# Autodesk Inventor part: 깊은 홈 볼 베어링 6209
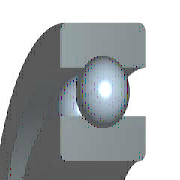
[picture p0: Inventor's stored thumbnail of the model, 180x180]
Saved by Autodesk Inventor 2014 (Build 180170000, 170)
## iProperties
IsCustomPart: 1
Created: 2012-02
Part Number: 깊은 홈 볼 베어링 6209
Material: 강철, 연강
Description: 깊은 그루부 볼 베어링
Document SubType Name: Modeling
Standard: JIS B 1521
Designer: mdu-01
Standards Organization: JIS
Language: ko-KR
Size Designation: 6209 45x85x19
Categories: <MemberInstance><Categories><Category DisplayName="샤프트 부품" InternalName="7f7aeb1f-a693-4053-b835-cee3144e0d98" Mnemonic="SHFT"><Category DisplayName="베어링" Inter
Density: 7.86 g/cm^3
Appearance: 강철(1)
Mass: 366.455 g
Surface Area: 242.591 cm^2
Volume: 46.6228 cm^3
Author: mdu-01
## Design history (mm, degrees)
sketch "스케치" dims "d0" = 10.4 (= -0.26 x WD + 0.26 x BD)
  geometry: L1 (4.3, 32.5)-(14.7, 32.5); L2 (9.5, 32.5)-(9.5, 27.3); L3 (9.5, 32.5)-(9.5, 37.7); L4 (5.636, 29.02)-(0, 29.02); L5 (0, 22.5)-(19, 22.5); L6 (5.636, 35.98)-(0, 35.98); L7 (0, 42.5)-(19, 42.5); L8 (19, 22.5)-(19, 29.02); L9 (13.364, 29.02)-(19, 29.02); L10 (13.364, 35.98)-(19, 35.98); L11 (19, 42.5)-(19, 35.98); L12 (-1.4, 0)-(8.4, 0) reference; L13 (0, -0.3)-(0, 5.3) reference
  constraints: 22 end point, 4 point on line, 2 collinear, 2 perpendicular, 2 symmetric about line, 1 midpoint, 1 parallel, 14 other
  dimensions: "d9" = 45 diameter of L5 L12 (= WD); "d11" = 85 diameter of L7 L12 (= BD); "d12" = 19 distance between parallel lines of L8 L13 (= KB); "d13" = 58.04 diameter of L9 L12 (= 0.326 x BD + 0.674 x WD)
revolve "본체" stored, may be unused: angle "d6" = 90 deg
revolve "볼" stored, may be unused: angle "d7" = 90 deg
pattern_circular "IDS_ARRAYBALL[SIMPL:T]" dims angle "d3" = 360 deg
body "Solid1"
fillet "모깎기1" dims "d1" = 1.1 (= KRS)
other parameters: "WD" = 45 [user parameter; used in 5 equation terms], "BD" = 85 [user parameter; used in 5 equation terms], "KB" = 19 [user parameter; used in 1 equation term], "KRS" = 1.1 [user parameter; used in 1 equation term], "d4" = 0, "d5" = 0, "d8" = 0, "d14" = 0, "d15" = 0, "BBA" = 0 [user parameter], "BC0" = 2.16e+07 [user parameter], "BC" = 3.32e+07 [user parameter], "BR" = 42.5 (= 0.5 x BD) [user parameter], "WR" = 22.5 (= 0.5 x WD) [user parameter]
